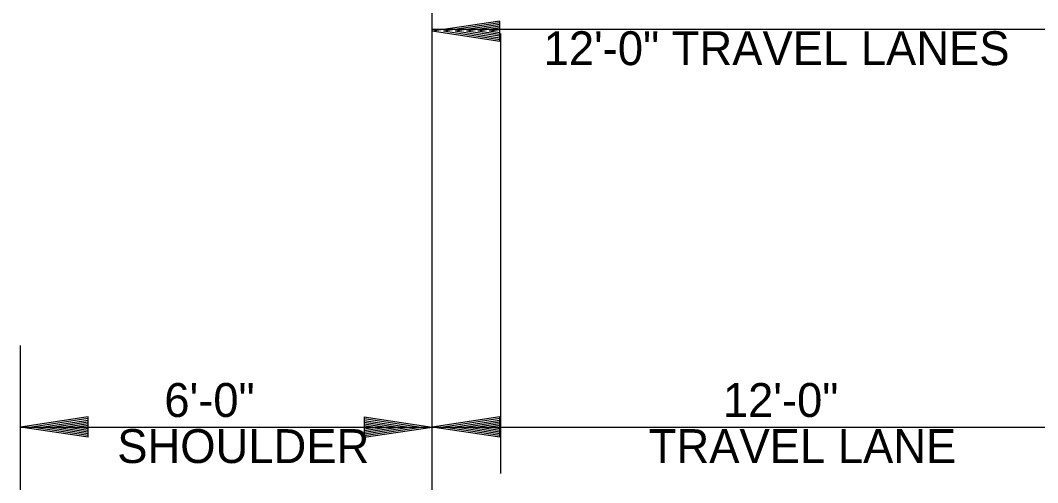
# Model space of a CAD drawing. Extents: x 6125 to 14104, y 8730 to 11067.
# Drawn here: x 8670.1 to 8970, y 10658.1 to 10794.6 of the extents above; entities that cross this region are included whole.
import ezdxf

# ---------------------------------------------------------------- set-up
doc = ezdxf.new("R2010")
doc.units = 0
doc.layers.add('Stage 1 Construction', color=7, linetype='Continuous')

msp = doc.modelspace()

# ---------------------------------------------------------------- linework, layer by layer
at = {"layer": 'Stage 1 Construction'}
for p, q in [((8791.5, 10637.08), (8791.5, 10928.28)), ((8811.5, 10794.37), (8791.5, 10791.37)), ((8791.5, 10791.97), (9005.34, 10791.97)), ((8811.5, 10793.87), (8794.84, 10791.37)), ((8811.5, 10793.36), (8798.28, 10791.37)), ((8811.5, 10792.86), (8801.61, 10791.37)), ((8811.5, 10792.35), (8805, 10791.37)), ((8811.5, 10791.84), (8808.34, 10791.37)), ((8811.5, 10788.37), (8811.5, 10794.37)), ((8811.5, 10788.37), (8791.5, 10791.37)), ((8811.5, 10788.87), (8794.84, 10791.37)), ((8811.5, 10789.38), (8798.28, 10791.37)), ((8811.5, 10789.88), (8801.61, 10791.37)), ((8811.5, 10790.4), (8805, 10791.37)), ((8811.5, 10790.9), (8808.34, 10791.37)), ((8811.77, 10660.86), (8811.77, 10790.71)), ((8670.1, 10543.29), (8670.1, 10698.6)), ((8791.5, 10637.08), (8791.5, 10698.6)), ((8690.1, 10677.54), (8670.1, 10674.54)), ((8690.1, 10677.54), (8670.1, 10674.54)), ((8690.1, 10677.04), (8673.44, 10674.54)), ((8690.1, 10677.04), (8673.44, 10674.54)), ((8690.1, 10676.53), (8676.88, 10674.54)), ((8690.1, 10676.53), (8676.88, 10674.54)), ((8690.1, 10676.03), (8680.21, 10674.54)), ((8690.1, 10676.03), (8680.21, 10674.54)), ((8690.1, 10675.52), (8683.6, 10674.54)), ((8690.1, 10675.52), (8683.6, 10674.54)), ((8690.1, 10675.01), (8686.94, 10674.54)), ((8690.1, 10675.01), (8686.94, 10674.54)), ((8690.1, 10671.54), (8690.1, 10677.54)), ((8690.1, 10671.54), (8690.1, 10677.54)), ((8771.5, 10677.54), (8791.5, 10674.54)), ((8771.5, 10677.54), (8771.5, 10671.54)), ((8771.5, 10677.54), (8791.5, 10674.54)), ((8771.5, 10677.54), (8771.5, 10671.54)), ((8771.5, 10677.04), (8788.16, 10674.54)), ((8771.5, 10677.04), (8788.16, 10674.54)), ((8771.5, 10676.53), (8784.72, 10674.54)), ((8771.5, 10676.53), (8784.72, 10674.54)), ((8771.5, 10676.03), (8781.39, 10674.54)), ((8771.5, 10676.03), (8781.39, 10674.54)), ((8771.5, 10675.51), (8778, 10674.54)), ((8771.5, 10675.51), (8778, 10674.54)), ((8771.5, 10675.01), (8774.66, 10674.54)), ((8771.5, 10675.01), (8774.66, 10674.54)), ((8811.5, 10677.54), (8791.5, 10674.54)), ((8811.5, 10677.54), (8791.5, 10674.54)), ((8811.5, 10677.04), (8794.84, 10674.54)), ((8811.5, 10677.04), (8794.84, 10674.54)), ((8811.5, 10676.53), (8798.28, 10674.54)), ((8811.5, 10676.53), (8798.28, 10674.54)), ((8811.5, 10676.03), (8801.61, 10674.54)), ((8811.5, 10676.03), (8801.61, 10674.54)), ((8811.5, 10675.52), (8805, 10674.54)), ((8811.5, 10675.52), (8805, 10674.54)), ((8811.5, 10675.01), (8808.34, 10674.54)), ((8811.5, 10675.01), (8808.34, 10674.54)), ((8811.5, 10671.54), (8811.5, 10677.54)), ((8811.5, 10671.54), (8811.5, 10677.54)), ((8670.1, 10674.54), (8791.5, 10674.54)), ((8690.1, 10671.54), (8670.1, 10674.54)), ((8690.1, 10671.54), (8670.1, 10674.54)), ((8690.1, 10672.04), (8673.44, 10674.54)), ((8690.1, 10672.04), (8673.44, 10674.54)), ((8690.1, 10672.55), (8676.88, 10674.54)), ((8690.1, 10672.55), (8676.88, 10674.54)), ((8690.1, 10673.05), (8680.21, 10674.54)), ((8690.1, 10673.05), (8680.21, 10674.54)), ((8690.1, 10673.57), (8683.6, 10674.54)), ((8690.1, 10673.57), (8683.6, 10674.54)), ((8690.1, 10674.07), (8686.94, 10674.54)), ((8690.1, 10674.07), (8686.94, 10674.54)), ((8771.5, 10671.54), (8791.5, 10674.54)), ((8771.5, 10673.56), (8778, 10674.54)), ((8771.5, 10672.55), (8784.72, 10674.54)), ((8771.5, 10672.04), (8788.16, 10674.54)), ((8771.5, 10673.05), (8781.39, 10674.54)), ((8771.5, 10674.07), (8774.66, 10674.54)), ((8771.5, 10671.54), (8791.5, 10674.54)), ((8771.5, 10673.56), (8778, 10674.54)), ((8771.5, 10672.55), (8784.72, 10674.54)), ((8771.5, 10672.04), (8788.16, 10674.54)), ((8771.5, 10673.05), (8781.39, 10674.54)), ((8771.5, 10674.07), (8774.66, 10674.54)), ((8791.5, 10674.54), (9005.34, 10674.54)), ((8811.5, 10671.54), (8791.5, 10674.54)), ((8811.5, 10671.54), (8791.5, 10674.54)), ((8811.5, 10672.04), (8794.84, 10674.54)), ((8811.5, 10672.04), (8794.84, 10674.54)), ((8811.5, 10672.55), (8798.28, 10674.54)), ((8811.5, 10672.55), (8798.28, 10674.54)), ((8811.5, 10673.05), (8801.61, 10674.54)), ((8811.5, 10673.05), (8801.61, 10674.54)), ((8811.5, 10673.57), (8805, 10674.54)), ((8811.5, 10673.57), (8805, 10674.54)), ((8811.5, 10674.07), (8808.34, 10674.54)), ((8811.5, 10674.07), (8808.34, 10674.54))]:
    msp.add_line(p, q, dxfattribs=at)

# ---------------------------------------------------------------- texts
for s, p in [('12\'-0" TRAVEL LANES', (8824.38, 10781.37)), ('6\'-0"', (8712.55, 10677.54)), ('12\'-0"', (8877.22, 10677.54)), ('SHOULDER', (8698.67, 10663.94)), ('TRAVEL LANE', (8855.38, 10663.94))]:
    msp.add_text(s, height=10, dxfattribs=at).set_placement(p)

doc.saveas('drawing.dxf')
